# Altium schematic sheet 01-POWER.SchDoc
size A4
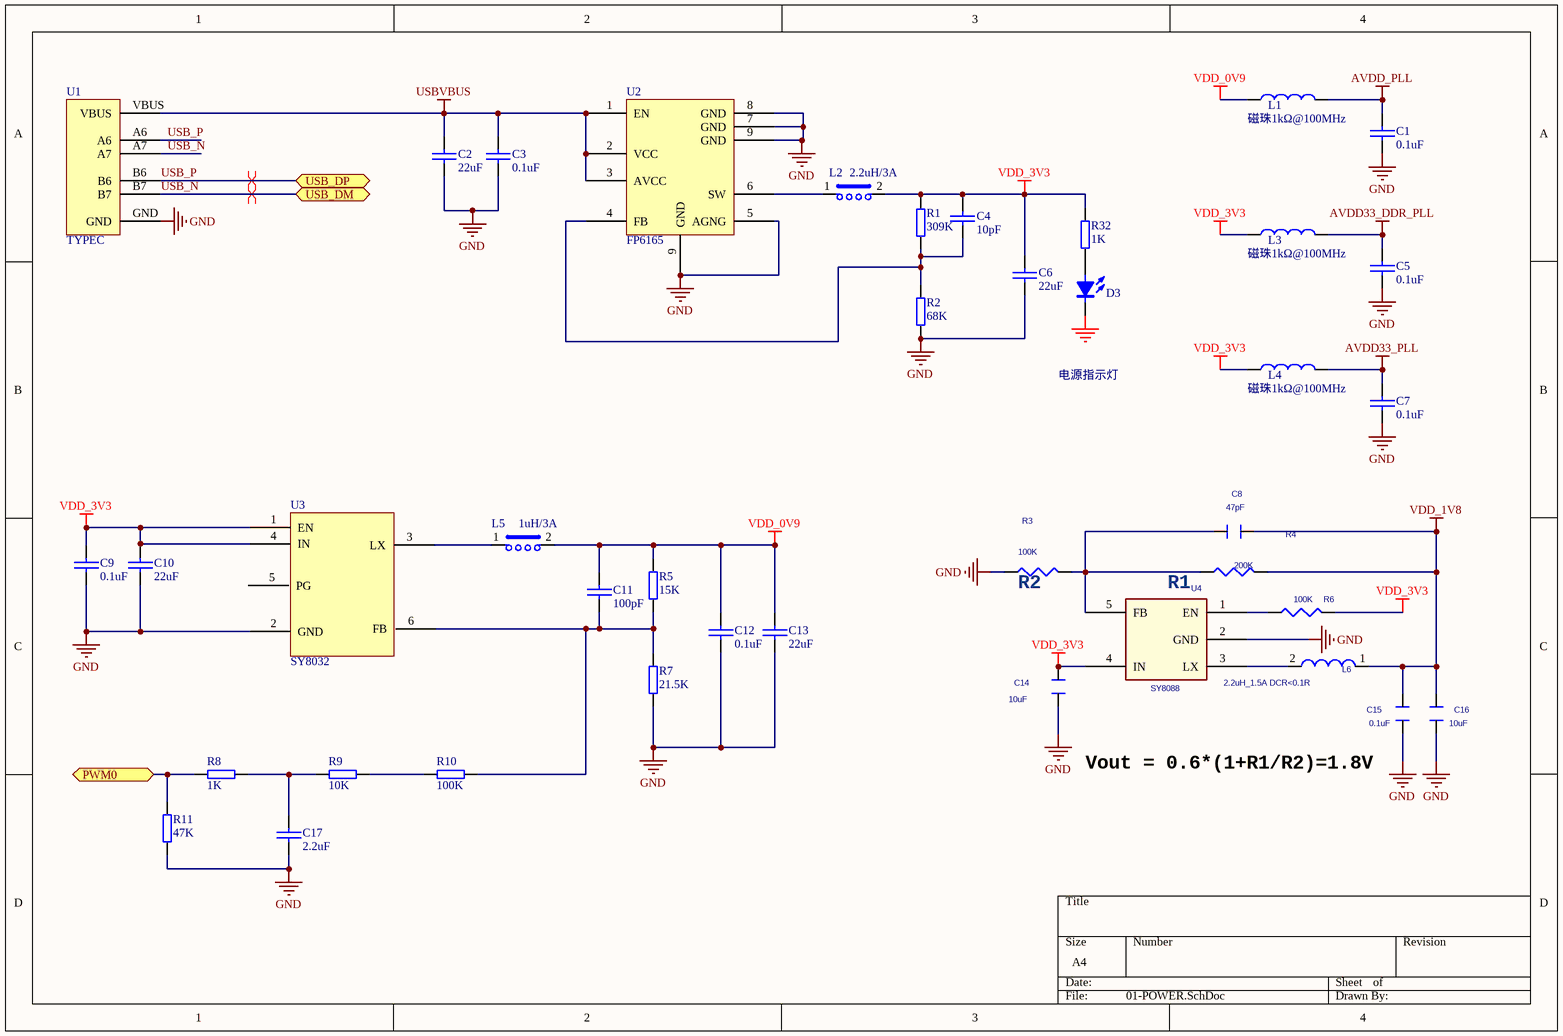
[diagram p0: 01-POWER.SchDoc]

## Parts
C1  0.1uF  [C0402]
C2  22uF  [C0805]
C3  0.1uF  [C0402]
C4  10pF  [C0402]
C5  0.1uF  [C0402]
C6  22uF  [C0805]
C7  0.1uF  [C0402]
C8  47pF  [C0402]
C9  0.1uF  [C0402]
C10  22uF  [C0805]
C11  100pF  [C0402]
C12  0.1uF  [C0402]
C13  22uF  [C0805]
C14  10uF  [C0603]
C15  0.1uF  [C0402]
C16  10uF  [C0603]
C17  2.2uF  [C0402]
D3  二极管(LED,红色)  [D0603]  (value not drawn)
L1  磁珠1kΩ@100MHz  [L0603]
L2  2.2uH/3A  [L-4.0S]
L3  磁珠1kΩ@100MHz  [L0603]
L4  磁珠1kΩ@100MHz  [L0603]
L5  1uH/3A  [L-4.0S]
L6  2.2uH_1.5A DCR<0.1R  [L-4.0S]
R1  309K  [R0402]
R2  68K  [R0402]
R3  100K  [R0402]
R4  200K  [R0402]
R5  15K  [R0402]
R6  100K  [R0402]
R7  21.5K  [R0402]
R8  1K  [R0402]
R9  10K  [R0402]
R10  100K  [R0402]
R11  47K  [R0402]
R32  1K  [R0402]
U1  TYPEC  [TYPC16PS]
U2  FP6165  [SOP-8(PAD)]
U3  SY8032  [SOT23-6]
U4  SY8088  [SOT23-5]

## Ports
PWM0 (bidir), USB_DM (bidir), USB_DP (bidir)

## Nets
AVDD33_DDR_PLL: C5.1 L3.2
AVDD33_PLL: C7.1 L4.2
AVDD_PLL: C1.1 L1.2
GND: C1.2 C2.1 C3.2 C5.2 C6.1 C7.2 C9.2 C10.1 C12.2 C13.1 C14.2 C15.2 C16.2 C17.2 D3.2(K) R2.1 R3.2 R7.1 R11.2 U1.GND U2.5(AGNG) U2.7(GND) U2.8(GND) U2.9(GND) U3.2(GND) U4.2(GND)
USBVBUS: C2.2 C3.1 U1.VBUS U2.1(EN) U2.2(VCC) U2.3(AVCC)
VDD_0V9: C11.1 C12.1 C13.2 L1.1 L5.2 R5.2
VDD_1V8: C8.1 C15.1 C16.1 L6.1 R4.1
VDD_3V3: C4.1 C6.2 C9.1 C10.2 C14.1 L2.2 L3.1 L4.1 R1.2 R6.1 R32.2 U3.1(EN) U3.4(IN) U4.4(IN)
PWM0: R8.2 R11.1 ; port PWM0
USB_N: U1.A7 U1.B7 ; port USB_DM
USB_P: U1.A6 U1.B6 ; port USB_DP
NetC4_2: C4.2 R1.1 R2.2 U2.4(FB)
NetC8_2: C8.2 R3.1 R4.2 U4.5(FB)
NetC11_2: C11.2 R5.1 R7.2 R10.1 U3.6(FB)
NetC17_1: C17.1 R8.1 R9.2
NetD3_1: D3.1(A) R32.1
NetL2_1: L2.1 U2.6(SW)
NetL5_1: L5.1 U3.3(LX)
NetL6_2: L6.2 U4.3(LX)
NetR6_2: R6.2 U4.1(EN)
NetR9_1: R9.1 R10.2

Not connected (* = marked no-connect by the designer): U3 5(PG)

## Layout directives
differential pair: USB_P
differential pair; rule Width MAXLIMIT=10mil MINLIMIT=6mil PREFEREDWIDTH=6mil: USB_N

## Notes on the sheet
- 电源指示灯
- (near R3) R2           R1
- Vout = 0.6*(1+R1/R2)=1.8V

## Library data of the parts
C1-C7 C9-C13 C17 = 电容: Capacitor
C8 C15 = CAPACITOR_1: ROOM: DCDC; PAGE: 5
C14 = CAPACITOR_3: PAGE: 5; ROOM: DCDC
C16 = CAPACITOR_3: ROOM: DCDC; PAGE: 5
D3 = 二极管(LED): Light-Emitting Diode
L1 L3 L4 = 电感: Inductor
L2 L5 = 电感(功率电感): 252012CDMCD
L6 = INDUCTOR_Dup1: ROOM: DCDC; PAGE: 5
R1 R2 R5 R7-R11 R32 = 电阻Ω: Resistor
R3 R6 = R_Dup4: ROOM: DCDC; PAGE: 5
R4 = R_Dup4: PAGE: 5; ROOM: DCDC
U4 = RT9293B_0: PAGE: 5; ROOM: DCDC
